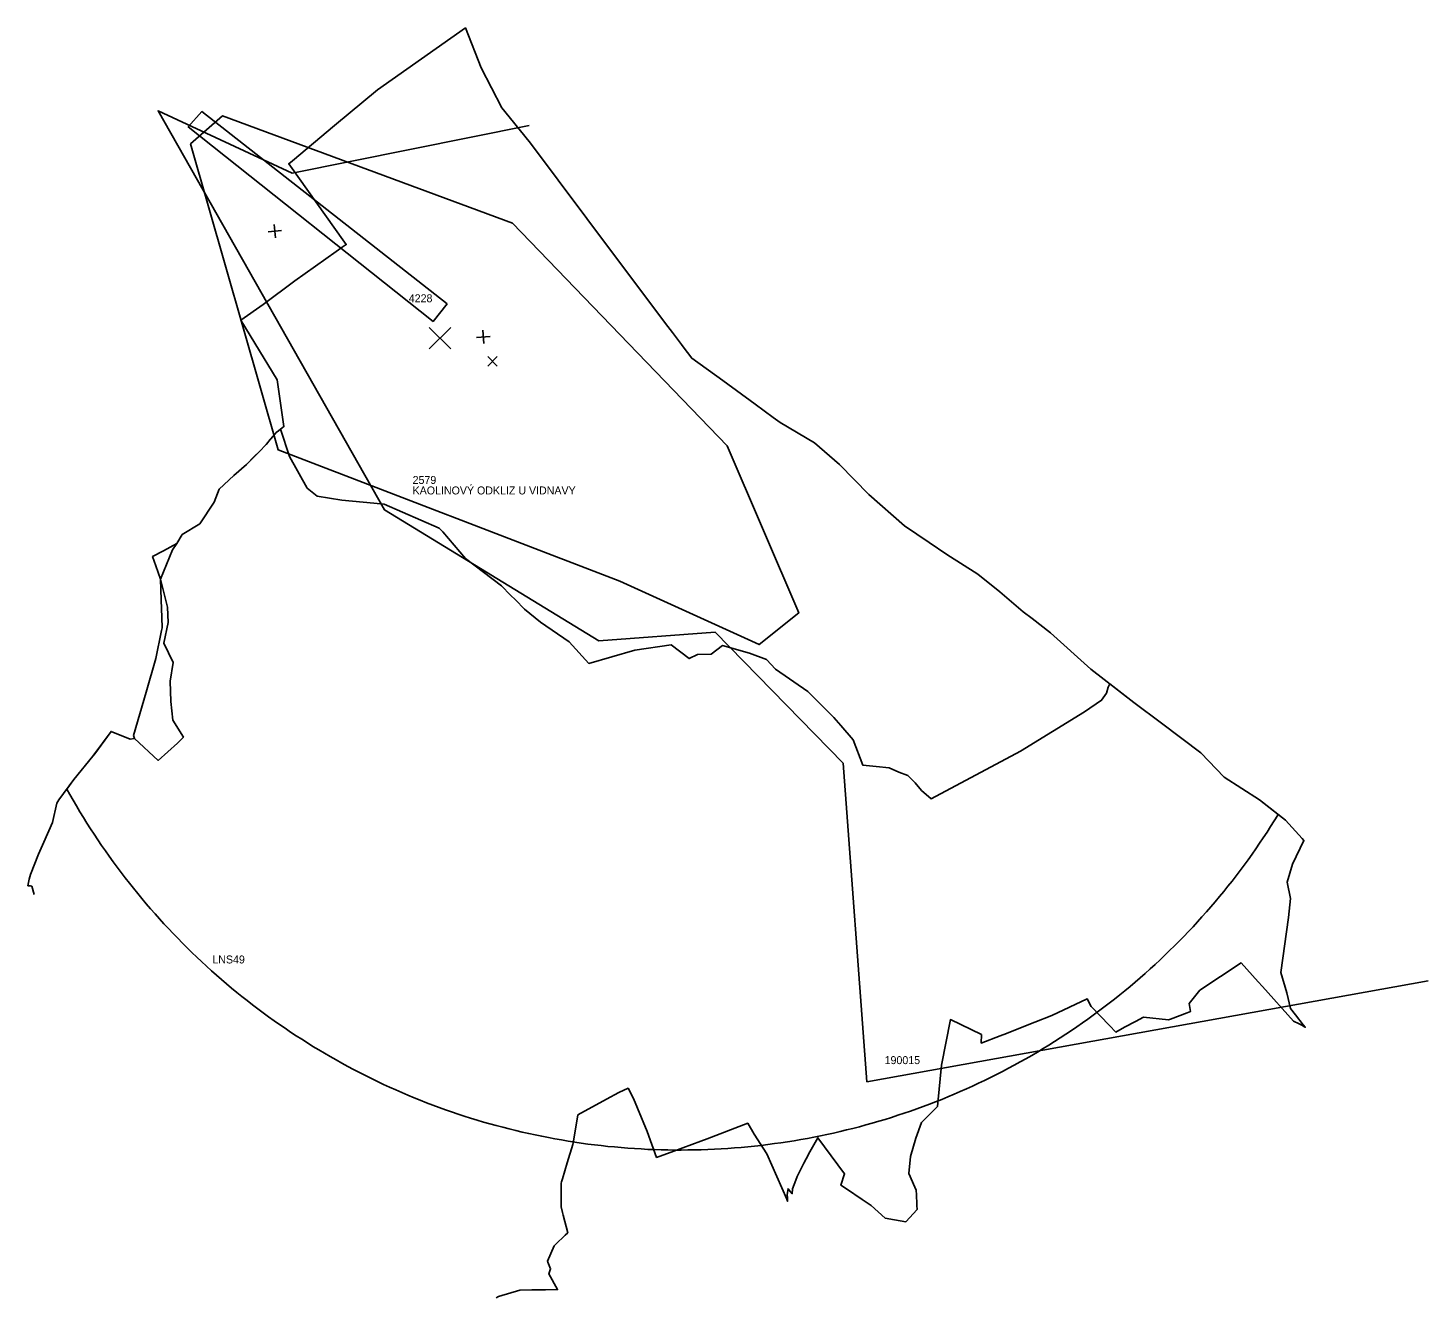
# Model space of a CAD drawing. Extents: x -556199 to -540209, y -1046851 to -1035695.
# Drawn here: x -543675 to -541914, y -1037292 to -1035695 of the extents above; entities that cross this region are included whole.
import ezdxf

# ---------------------------------------------------------------- set-up
doc = ezdxf.new("R2010")
doc.units = 0
for name, color, linetype in [('ft_08_KOMS_rr_trasa_l_RRT_STAV', 7, 'Continuous'), ('Vrstva 25', 7, 'Continuous'), ('Vrstva 46', 7, 'Continuous'), ('Vrstva 48', 7, 'Continuous'), ('Vrstva 50', 7, 'Continuous'), ('Vrstva 53', 7, 'Continuous')]:
    doc.layers.add(name, color=color, linetype=linetype)

msp = doc.modelspace()

# ---------------------------------------------------------------- linework, layer by layer
at = {"layer": 'ft_08_KOMS_rr_trasa_l_RRT_STAV'}
for p, q in [((-543355.6, -1035949.1), (-543372.5, -1035950.7)), ((-543364.9, -1035941.5), (-543363.2, -1035958.4)), ((-543169.8, -1036071.2), (-543142.8, -1036098.2)), ((-543142.8, -1036071.2), (-543169.8, -1036098.2)), ((-543102.5, -1036074.6), (-543101.2, -1036091.5)), ((-543093.4, -1036082.3), (-543110.3, -1036083.7)), ((-543096.3, -1036107.7), (-543084.3, -1036119.7)), ((-543084.3, -1036107.7), (-543096.3, -1036119.7))]:
    msp.add_line(p, q, dxfattribs=at)
at = {"layer": 'Vrstva 25'}
msp.add_lwpolyline([(-543085.7, -1037291.6), (-543082.6, -1037289.8), (-543056.1, -1037281.6), (-543040.8, -1037281.4), (-543023.7, -1037281.2), (-543008.4, -1037281), (-543019.5, -1037261.3), (-543017.2, -1037254.8), (-543020.5, -1037246.5), (-543021.1, -1037245.2), (-543012.8, -1037225.9), (-543008.7, -1037221.9), (-543008, -1037221.3), (-543006.9, -1037220.2), (-543003.3, -1037216.8), (-542998.8, -1037212.5), (-542995.6, -1037209.5), (-543001.3, -1037187.3), (-543002.1, -1037184.1), (-543003.9, -1037176.9), (-543004, -1037159.9), (-543004, -1037158), (-543004, -1037148.2), (-543003.8, -1037147.2), (-543003.5, -1037145.4), (-543002.4, -1037141.9), (-542996.2, -1037121.7), (-542989.1, -1037098.5), (-542988, -1037091.9), (-542982.9, -1037061.3), (-542946.9, -1037041.7), (-542931.3, -1037033.2), (-542919.7, -1037027.9), (-542913, -1037040.9), (-542907.9, -1037053.1), (-542895.8, -1037082.1), (-542883.9, -1037114.9), (-542862.3, -1037106.9), (-542828.4, -1037094.3), (-542820.5, -1037091.3), (-542769.2, -1037071.9), (-542761, -1037085.5), (-542745.4, -1037110.5), (-542720.3, -1037167.3), (-542719.2, -1037169.9), (-542719.4, -1037165.5), (-542719.7, -1037161.6), (-542718.6, -1037154.2), (-542715.3, -1037158.1), (-542713.3, -1037160.5), (-542713.1, -1037154.2), (-542713.1, -1037154.2), (-542708.9, -1037143.3), (-542707.2, -1037139), (-542698.5, -1037122.2), (-542695.6, -1037116.7), (-542691, -1037108), (-542680.9, -1037090.2), (-542647.4, -1037135.5), (-542652, -1037149.8), (-542645.1, -1037154.4), (-542625.3, -1037167.8), (-542614.1, -1037175.4), (-542596.2, -1037191.2), (-542584.5, -1037193.3), (-542570.5, -1037195.8), (-542556.3, -1037180.3), (-542556.6, -1037175.2), (-542556.7, -1037172.2), (-542557.2, -1037163), (-542557.2, -1037161.7), (-542557.5, -1037156), (-542559.1, -1037152.3), (-542566.8, -1037135), (-542564.6, -1037113.6), (-542557.9, -1037090.6), (-542550.8, -1037070.8), (-542534.5, -1037054.5), (-542530.6, -1037050.6), (-542530.2, -1037046.1), (-542525.7, -1036998.8), (-542514.4, -1036941.4), (-542475.4, -1036960.3), (-542475.3, -1036960.4), (-542475.5, -1036971), (-542451.7, -1036961.8), (-542443.7, -1036958.8), (-542438.8, -1036956.8), (-542408.2, -1036944.8), (-542386.6, -1036936.3), (-542342.3, -1036915.6), (-542337.3, -1036925.1), (-542314.2, -1036949.1), (-542306.4, -1036957.2), (-542295.2, -1036951.2), (-542281.5, -1036943.8), (-542271.6, -1036938.4), (-542240.2, -1036942), (-542237.7, -1036941.1), (-542216.6, -1036933.1), (-542212.5, -1036931.5), (-542214.1, -1036921.3), (-542200.5, -1036904.7), (-542148.6, -1036870.2), (-542141.7, -1036877.9), (-542127.3, -1036894), (-542121.9, -1036900.1), (-542083, -1036943.6), (-542075.7, -1036946.8), (-542072.5, -1036948.6), (-542069.1, -1036950.6), (-542068.1, -1036951.1), (-542070.5, -1036948.1), (-542080.4, -1036935.6), (-542086.7, -1036927.6), (-542091.1, -1036907.9), (-542098.6, -1036882.2), (-542089.2, -1036813.1), (-542086.7, -1036789.2), (-542090.6, -1036768.7), (-542084.1, -1036745.9), (-542069.8, -1036716.4), (-542072.1, -1036713.8), (-542092.8, -1036690.7), (-542125.6, -1036665.3), (-542169.9, -1036636.7), (-542199.3, -1036606), (-542248.8, -1036568.9), (-542283.5, -1036542.7), (-542314, -1036519.2), (-542316.1, -1036523.3), (-542317.9, -1036531.1), (-542324.2, -1036540), (-542345.7, -1036554.4), (-542426.2, -1036604.1), (-542538.7, -1036663.7), (-542550.6, -1036653.3), (-542558.7, -1036643.7), (-542568, -1036634.4), (-542579.4, -1036630.4), (-542591.3, -1036624.8), (-542607.6, -1036623.3), (-542624.4, -1036621.6), (-542636.6, -1036589.7), (-542652.1, -1036571.8), (-542660.8, -1036561.8), (-542693.8, -1036529), (-542734.2, -1036500.8), (-542745.5, -1036488.6), (-542767.1, -1036480.6), (-542801.1, -1036471.2), (-542815.1, -1036482), (-542832.6, -1036482.3), (-542843.1, -1036487.6), (-542865.6, -1036470.3), (-542911.4, -1036477.1), (-542969.2, -1036493.7), (-542994, -1036466.4), (-543029.9, -1036441.8), (-543050, -1036425.5), (-543061.5, -1036413.8), (-543067.5, -1036407.6), (-543079, -1036395.9), (-543124.2, -1036361.7), (-543152.7, -1036328), (-543157.3, -1036323.6), (-543226.5, -1036293.2), (-543239.7, -1036292.1), (-543279.8, -1036288.3), (-543310.7, -1036283.2), (-543319.4, -1036276.6), (-543323.6, -1036273.2), (-543345.5, -1036233.3), (-543356.8, -1036199), (-543359.4, -1036201.1), (-543362.4, -1036203.4), (-543363.8, -1036205), (-543372.1, -1036214.7), (-543372.5, -1036215.2), (-543374.9, -1036218.2), (-543375.3, -1036218.6), (-543383.5, -1036226.9), (-543389.5, -1036233), (-543399.7, -1036243.4), (-543415.6, -1036257.2), (-543434.2, -1036274.3), (-543440.4, -1036290.8), (-543458.3, -1036318), (-543480.5, -1036331.6), (-543487.3, -1036342.7), (-543504.2, -1036351.9), (-543517.8, -1036359.3), (-543513.9, -1036370.7), (-543508.1, -1036387.7), (-543507.2, -1036413.8), (-543506.4, -1036435.9), (-543506, -1036448.8), (-543506.7, -1036452.1), (-543513.6, -1036487.5), (-543525.9, -1036529.6), (-543541.8, -1036584.1), (-543540.8, -1036587.9), (-543546.1, -1036588.7), (-543570, -1036579.1), (-543590.7, -1036607.1), (-543592.9, -1036610.1), (-543617, -1036639.6), (-543635.6, -1036665.3), (-543638.4, -1036669.3), (-543643.6, -1036693.8), (-543654.6, -1036718.2), (-543661.4, -1036733.6), (-543671.5, -1036759.2), (-543673.1, -1036765.1), (-543674.6, -1036773.2), (-543671.6, -1036773.2), (-543669.8, -1036773.8), (-543666.6, -1036784.2)], dxfattribs=at)
at = {"layer": 'Vrstva 46'}
msp.add_lwpolyline([(-543044.2, -1035817.1), (-543342.3, -1035877.2), (-543510.9, -1035798.6), (-543226.2, -1036300.5), (-542956.5, -1036465.3), (-542810.4, -1036454.1), (-542649.3, -1036618.9), (-542619.3, -1037019.7), (-541913.6, -1036892.8)], dxfattribs=at)
at = {"layer": 'Vrstva 48'}
msp.add_lwpolyline([(-543625.8, -1036651.7), (-543622, -1036658.4), (-543617.9, -1036665.7), (-543613.6, -1036672.9), (-543609.3, -1036680.1), (-543604.9, -1036687.3), (-543600.5, -1036694.4), (-543596, -1036701.5), (-543591.4, -1036708.5), (-543586.7, -1036715.5), (-543582, -1036722.5), (-543577.2, -1036729.4), (-543572.4, -1036736.2), (-543567.4, -1036743.1), (-543562.5, -1036749.8), (-543557.4, -1036756.5), (-543552.3, -1036763.2), (-543547.1, -1036769.8), (-543541.9, -1036776.4), (-543536.6, -1036782.9), (-543531.3, -1036789.4), (-543525.8, -1036795.8), (-543520.4, -1036802.2), (-543514.8, -1036808.5), (-543509.2, -1036814.7), (-543503.6, -1036821), (-543497.8, -1036827.1), (-543492.1, -1036833.2), (-543486.2, -1036839.3), (-543480.3, -1036845.2), (-543474.4, -1036851.2), (-543468.4, -1036857), (-543462.3, -1036862.9), (-543456.2, -1036868.6), (-543450, -1036874.3), (-543443.8, -1036880), (-543437.5, -1036885.5), (-543431.2, -1036891.1), (-543424.8, -1036896.5), (-543418.4, -1036901.9), (-543411.9, -1036907.3), (-543405.4, -1036912.5), (-543398.8, -1036917.7), (-543392.1, -1036922.9), (-543385.5, -1036928), (-543378.7, -1036933), (-543371.9, -1036938), (-543365.1, -1036942.9), (-543358.2, -1036947.7), (-543351.3, -1036952.5), (-543344.4, -1036957.2), (-543337.4, -1036961.8), (-543330.3, -1036966.3), (-543323.2, -1036970.8), (-543316.1, -1036975.3), (-543308.9, -1036979.6), (-543301.7, -1036983.9), (-543294.4, -1036988.1), (-543287.1, -1036992.3), (-543279.8, -1036996.4), (-543272.4, -1037000.4), (-543265, -1037004.3), (-543257.5, -1037008.2), (-543250, -1037012), (-543242.5, -1037015.7), (-543234.9, -1037019.4), (-543227.3, -1037023), (-543219.7, -1037026.5), (-543212, -1037029.9), (-543204.3, -1037033.3), (-543196.6, -1037036.6), (-543188.9, -1037039.8), (-543181.1, -1037043), (-543173.3, -1037046), (-543165.4, -1037049), (-543157.5, -1037052), (-543149.6, -1037054.8), (-543141.7, -1037057.6), (-543133.7, -1037060.3), (-543125.8, -1037062.9), (-543117.8, -1037065.4), (-543109.7, -1037067.9), (-543101.7, -1037070.3), (-543093.6, -1037072.6), (-543085.5, -1037074.8), (-543077.4, -1037077), (-543069.2, -1037079.1), (-543061.1, -1037081.1), (-543052.9, -1037083), (-543044.7, -1037084.9), (-543036.5, -1037086.6), (-543028.3, -1037088.3), (-543020, -1037089.9), (-543011.8, -1037091.5), (-543003.5, -1037092.9), (-542995.2, -1037094.3), (-542986.9, -1037095.6), (-542978.6, -1037096.8), (-542970.3, -1037098), (-542962, -1037099), (-542953.6, -1037100), (-542945.3, -1037100.9), (-542936.9, -1037101.7), (-542928.5, -1037102.5), (-542920.2, -1037103.2), (-542911.8, -1037103.7), (-542903.4, -1037104.2), (-542895, -1037104.7), (-542886.6, -1037105), (-542878.2, -1037105.3), (-542869.8, -1037105.5), (-542861.4, -1037105.6), (-542853, -1037105.6), (-542844.6, -1037105.5), (-542836.2, -1037105.4), (-542827.8, -1037105.2), (-542819.4, -1037104.9), (-542811, -1037104.5), (-542802.6, -1037104.1), (-542794.3, -1037103.5), (-542785.9, -1037102.9), (-542777.5, -1037102.2), (-542769.2, -1037101.4), (-542760.8, -1037100.6), (-542752.4, -1037099.7), (-542744.1, -1037098.6), (-542735.8, -1037097.5), (-542727.5, -1037096.4), (-542719.2, -1037095.1), (-542710.9, -1037093.8), (-542702.6, -1037092.4), (-542694.3, -1037090.9), (-542686.1, -1037089.3), (-542677.8, -1037087.7), (-542669.6, -1037086), (-542661.4, -1037084.2), (-542653.2, -1037082.3), (-542645, -1037080.3), (-542636.9, -1037078.3), (-542628.8, -1037076.2), (-542620.7, -1037074), (-542612.6, -1037071.7), (-542604.5, -1037069.4), (-542596.5, -1037067), (-542588.4, -1037064.5), (-542580.4, -1037061.9), (-542572.5, -1037059.2), (-542564.5, -1037056.5), (-542556.6, -1037053.7), (-542548.7, -1037050.8), (-542540.8, -1037047.9), (-542533, -1037044.9), (-542525.2, -1037041.8), (-542517.4, -1037038.6), (-542509.7, -1037035.3), (-542502, -1037032), (-542494.3, -1037028.6), (-542486.6, -1037025.2), (-542479, -1037021.6), (-542471.4, -1037018), (-542463.9, -1037014.3), (-542456.4, -1037010.6), (-542448.9, -1037006.7), (-542441.4, -1037002.8), (-542434, -1036998.9), (-542426.7, -1036994.8), (-542419.4, -1036990.7), (-542412.1, -1036986.5), (-542404.8, -1036982.3), (-542397.6, -1036978), (-542390.5, -1036973.6), (-542383.3, -1036969.1), (-542376.3, -1036964.6), (-542369.2, -1036960), (-542362.2, -1036955.3), (-542355.3, -1036950.6), (-542348.4, -1036945.8), (-542341.5, -1036941), (-542334.7, -1036936.1), (-542328, -1036931.1), (-542321.2, -1036926), (-542314.6, -1036920.9), (-542308, -1036915.7), (-542301.4, -1036910.5), (-542294.9, -1036905.2), (-542288.4, -1036899.8), (-542282, -1036894.4), (-542275.6, -1036888.9), (-542269.3, -1036883.4), (-542263.1, -1036877.8), (-542256.9, -1036872.1), (-542250.7, -1036866.4), (-542244.6, -1036860.6), (-542238.6, -1036854.8), (-542232.6, -1036848.9), (-542226.7, -1036842.9), (-542220.8, -1036836.9), (-542215, -1036830.9), (-542209.2, -1036824.7), (-542203.5, -1036818.6), (-542197.9, -1036812.3), (-542192.3, -1036806.1), (-542186.8, -1036799.7), (-542181.3, -1036793.3), (-542175.9, -1036786.9), (-542170.6, -1036780.4), (-542165.3, -1036773.9), (-542160.1, -1036767.3), (-542155, -1036760.6), (-542149.9, -1036754), (-542144.9, -1036747.2), (-542139.9, -1036740.4), (-542135, -1036733.6), (-542130.2, -1036726.7), (-542125.5, -1036719.8), (-542120.8, -1036712.8), (-542116.1, -1036705.8), (-542111.6, -1036698.8), (-542107.1, -1036691.7), (-542102.7, -1036684.5), (-542102.1, -1036683.5), (-542125.6, -1036665.3), (-542169.9, -1036636.7), (-542199.3, -1036606), (-542248.8, -1036568.9), (-542283.5, -1036542.7), (-542337.9, -1036500.9), (-542388.3, -1036455), (-542411.4, -1036437.3), (-542422.8, -1036428.7), (-542452, -1036403.6), (-542480, -1036381.3), (-542519, -1036356.5), (-542540.9, -1036341.6), (-542571.9, -1036320.4), (-542617, -1036281.3), (-542653.7, -1036243.4), (-542685.1, -1036216.3), (-542728.5, -1036190.8), (-542737.3, -1036184.4), (-542760.1, -1036167.7), (-542800.8, -1036138), (-542839.6, -1036109.9), (-542850.5, -1036095.4), (-542852.5, -1036092.7), (-542864, -1036077.3), (-542869.7, -1036069.8), (-542936.7, -1035980.7), (-543042.6, -1035839.4), (-543069.2, -1035806.4), (-543078.5, -1035794.9), (-543104.7, -1035744.6), (-543124.3, -1035694.5), (-543234.9, -1035772.4), (-543289.2, -1035817), (-543341.9, -1035861.5), (-543346.5, -1035865.2), (-543276.4, -1035963.9), (-543274.2, -1035967), (-543279.3, -1035970.3), (-543286.8, -1035975.7), (-543338.8, -1036012.6), (-543378.7, -1036042.3), (-543406.7, -1036061.9), (-543389.2, -1036090.9), (-543361.3, -1036136.8), (-543352.7, -1036195.7), (-543356.8, -1036199), (-543359.4, -1036201.1), (-543362.4, -1036203.4), (-543363.8, -1036205), (-543372.1, -1036214.7), (-543372.5, -1036215.2), (-543374.9, -1036218.2), (-543375.3, -1036218.6), (-543383.5, -1036226.9), (-543399.7, -1036243.4), (-543415.6, -1036257.2), (-543434.2, -1036274.3), (-543440.4, -1036290.8), (-543458.3, -1036318), (-543480.5, -1036331.6), (-543487.3, -1036342.7), (-543492.9, -1036350.6), (-543508.1, -1036387.7), (-543499, -1036422.7), (-543498.1, -1036442.3), (-543503.8, -1036468), (-543491.9, -1036492.5), (-543495.7, -1036516.1), (-543494.8, -1036541.3), (-543492.5, -1036564.8), (-543479.1, -1036586.3), (-543486.5, -1036594), (-543510.9, -1036615.5), (-543540.8, -1036587.9), (-543546.1, -1036588.7), (-543570, -1036579.1), (-543592.9, -1036610.1), (-543617, -1036639.6), (-543625.8, -1036651.7)], dxfattribs=at)
at = {"layer": 'Vrstva 50'}
msp.add_lwpolyline([(-543065, -1035940), (-543430, -1035805), (-543470, -1035840), (-543360, -1036225), (-542930, -1036390), (-542755, -1036470), (-542705, -1036430), (-542795, -1036220), (-543065, -1035940)], dxfattribs=at)
at = {"layer": 'Vrstva 53'}
msp.add_lwpolyline([(-543147.3, -1036041.6), (-543165, -1036063.5), (-543472.9, -1035818.9), (-543456, -1035799.7)], close=True, dxfattribs=at)

# ---------------------------------------------------------------- texts
at = {"layer": 'Vrstva 46'}
msp.add_text('190015', height=10, dxfattribs=at).set_placement((-542597.1, -1036997.5))
at = {"layer": 'Vrstva 48'}
msp.add_text('LNS49', height=10, dxfattribs=at).set_placement((-543442.7, -1036870.9))
at = {"layer": 'Vrstva 50'}
for s, p in [('2579', (-543190.8, -1036267.9)), ('KAOLINOVÝ ODKLIZ U VIDNAVY', (-543190.8, -1036281.1))]:
    msp.add_text(s, height=10, dxfattribs=at).set_placement(p)
at = {"layer": 'Vrstva 53'}
msp.add_text('4228', height=10, dxfattribs=at).set_placement((-543195.6, -1036039.4))

doc.saveas('drawing.dxf')
